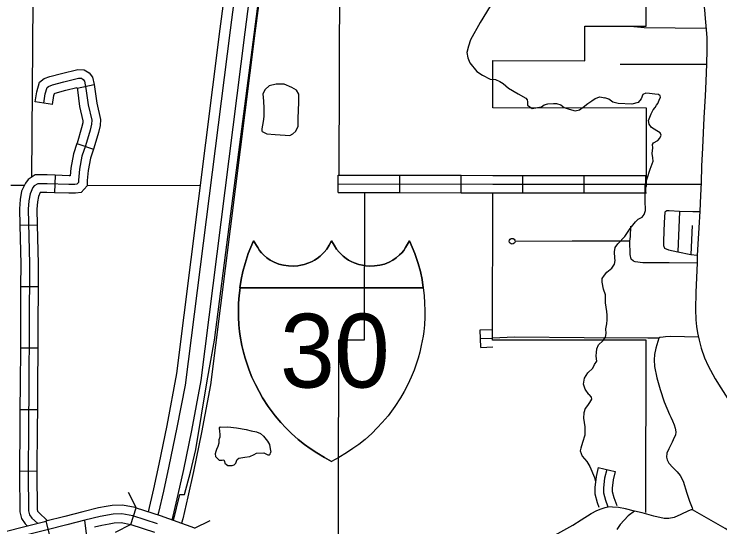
# Model space of a CAD drawing. Extents: x 813775 to 1157140, y 1757555 to 1979907.
# Drawn here: x 985663 to 997785, y 1859017 to 1867821 of the extents above; entities that cross this region are included whole.
import ezdxf

# ---------------------------------------------------------------- set-up
doc = ezdxf.new("R2010")
doc.units = 0
for name, color, linetype in [('Level 15', 7, 'Continuous'), ('Level 19', 7, 'Continuous'), ('Level 23', 7, 'Continuous'), ('Level 31', 7, 'Continuous'), ('Level 32', 7, 'Continuous'), ('Level 33', 7, 'Continuous'), ('Level 34', 7, 'Continuous'), ('Level 35', 7, 'Continuous'), ('Level 38', 7, 'Continuous'), ('Level 4', 7, 'Continuous'), ('Level 45', 7, 'Continuous'), ('Level 5', 7, 'Continuous'), ('Level 6', 7, 'Continuous'), ('Level 9', 7, 'Continuous')]:
    doc.layers.add(name, color=color, linetype=linetype)

msp = doc.modelspace()

# ---------------------------------------------------------------- linework, layer by layer
at = {"layer": 'Level 15'}
for points in [[(997102, 1871461), (997156, 1871024), (997216, 1870530), (997290, 1869822), (997389, 1868989), (997444, 1868499), (997480, 1868200), (997518, 1867894), (997531, 1867744), (997550, 1867556), (997558, 1867415), (997563, 1867292), (997560, 1867202), (997555, 1866966), (997541, 1866667), (997533, 1866416), (997511, 1866043), (997484, 1865525), (997470, 1865211), (997464, 1864930), (997453, 1864707), (997440, 1864440), (997423, 1864150), (997408, 1863873)], [(997408, 1863873), (997397, 1863676), (997393, 1863550), (997371, 1863040), (997368, 1862753), (997374, 1862572), (997381, 1862459), (997401, 1862349), (997429, 1862223), (997461, 1862088), (997523, 1861921), (997585, 1861780), (997703, 1861561), (997801, 1861403), (998031, 1861044), (998302, 1860636), (998495, 1860333), (998820, 1859828)]]:
    msp.add_lwpolyline(points, dxfattribs=at)
at = {"layer": 'Level 19'}
for points in [[(989204, 1867569), (989469, 1869607)], [(989637, 1869585), (989373, 1867548)], [(989631, 1867514), (989895, 1869552)], [(990064, 1869530), (989799, 1867492)], [(988455, 1861653), (989204, 1867569)], [(989373, 1867548), (988601, 1861451)], [(988873, 1861532), (989631, 1867514)], [(989799, 1867492), (989035, 1861457)], [(988061, 1859668), (988155, 1860095), (988293, 1860755), (988455, 1861653)], [(988480, 1859572), (988575, 1860003), (988714, 1860671), (988873, 1861532)], [(988601, 1861451), (988459, 1860722), (988321, 1860058), (988227, 1859630)], [(989035, 1861457), (988881, 1860637), (988741, 1859967), (988646, 1859534)], [(987971, 1859275), (988061, 1859668)], [(988227, 1859630), (988142, 1859264), (988131, 1859224)], [(988376, 1859137), (988394, 1859199), (988480, 1859572)], [(988646, 1859534), (988559, 1859156), (988537, 1859079)]]:
    msp.add_lwpolyline(points, dxfattribs=at)
at = {"layer": 'Level 23'}
msp.add_line((992691, 1863121), (992689, 1863121), dxfattribs=at)
for points in [[(989541, 1863121), (989563, 1863266), (989592, 1863404), (989629, 1863537), (989683, 1863708), (989776, 1863931), (989847, 1863813), (989878, 1863763), (989910, 1863724), (989948, 1863686), (990005, 1863638), (990063, 1863597), (990127, 1863561), (990209, 1863530), (990290, 1863510), (990376, 1863498), (990468, 1863496), (990534, 1863501), (990588, 1863508), (990646, 1863520), (990727, 1863550), (990780, 1863573), (990824, 1863596), (990867, 1863625), (990919, 1863665), (990986, 1863731), (991033, 1863788), (991072, 1863852), (991116, 1863928)], [(991116, 1863928), (991072, 1863852), (991033, 1863788), (990986, 1863731), (990919, 1863665), (990867, 1863625), (990824, 1863596), (990780, 1863573), (990727, 1863550), (990646, 1863520), (990588, 1863508), (990534, 1863501), (990468, 1863496), (990376, 1863498), (990290, 1863510), (990209, 1863530), (990127, 1863561), (990063, 1863597), (990005, 1863638), (989948, 1863686), (989910, 1863724), (989878, 1863763), (989847, 1863813), (989776, 1863931), (989683, 1863708), (989629, 1863537), (989592, 1863404), (989563, 1863266), (989541, 1863121)], [(991116, 1863928), (991159, 1863852), (991198, 1863788), (991246, 1863731), (991313, 1863665), (991364, 1863625), (991407, 1863596), (991451, 1863573), (991504, 1863550), (991586, 1863520), (991644, 1863508), (991698, 1863501), (991764, 1863496), (991855, 1863498), (991942, 1863510), (992022, 1863530), (992105, 1863561), (992168, 1863597), (992226, 1863638), (992283, 1863686), (992322, 1863724), (992354, 1863763), (992385, 1863813), (992455, 1863931), (992548, 1863708), (992602, 1863537), (992640, 1863404), (992669, 1863266), (992691, 1863121)], [(992691, 1863121), (992669, 1863266), (992640, 1863404), (992602, 1863537), (992548, 1863708), (992455, 1863931), (992385, 1863813), (992354, 1863763), (992322, 1863724), (992283, 1863686), (992226, 1863638), (992168, 1863597), (992105, 1863561), (992022, 1863530), (991942, 1863510), (991855, 1863498), (991764, 1863496), (991698, 1863501), (991644, 1863508), (991586, 1863520), (991504, 1863550), (991451, 1863573), (991407, 1863596), (991364, 1863625), (991313, 1863665), (991246, 1863731), (991198, 1863788), (991159, 1863852), (991116, 1863928)], [(989543, 1863121), (989527, 1862992), (989518, 1862857), (989514, 1862732), (989516, 1862619), (989523, 1862487), (989534, 1862373), (989546, 1862290), (989575, 1862130), (989602, 1862018), (989630, 1861916), (989663, 1861810), (989701, 1861705), (989747, 1861590), (989808, 1861459), (989869, 1861341), (989931, 1861233), (990027, 1861085), (990145, 1860926), (990245, 1860808), (990331, 1860715), (990427, 1860621), (990541, 1860519), (990648, 1860434), (990749, 1860360), (990860, 1860286), (990991, 1860208), (991116, 1860141)], [(991116, 1860141), (990991, 1860208), (990860, 1860286), (990749, 1860360), (990648, 1860434), (990541, 1860519), (990427, 1860621), (990331, 1860715), (990245, 1860808), (990145, 1860926), (990027, 1861085), (989931, 1861233), (989869, 1861341), (989808, 1861459), (989747, 1861590), (989701, 1861705), (989663, 1861810), (989630, 1861916), (989602, 1862018), (989575, 1862130), (989546, 1862290), (989534, 1862373), (989523, 1862487), (989516, 1862619), (989514, 1862732), (989518, 1862857), (989527, 1862992), (989543, 1863121)], [(992691, 1863121), (989541, 1863121)], [(989541, 1863121), (992691, 1863121)], [(989541, 1863121), (992691, 1863121)], [(992689, 1863121), (992704, 1862992), (992714, 1862857), (992717, 1862732), (992716, 1862619), (992709, 1862487), (992698, 1862373), (992686, 1862290), (992656, 1862130), (992630, 1862018), (992602, 1861916), (992569, 1861810), (992531, 1861705), (992484, 1861590), (992424, 1861459), (992362, 1861341), (992301, 1861233), (992204, 1861085), (992086, 1860926), (991987, 1860808), (991900, 1860715), (991805, 1860621), (991690, 1860519), (991584, 1860434), (991483, 1860360), (991372, 1860286), (991241, 1860208), (991116, 1860141)], [(992689, 1863121), (992704, 1862992), (992714, 1862857), (992717, 1862732), (992716, 1862619), (992709, 1862487), (992698, 1862373), (992686, 1862290), (992656, 1862130), (992630, 1862018), (992602, 1861916), (992569, 1861810), (992531, 1861705), (992484, 1861590), (992424, 1861459), (992362, 1861341), (992301, 1861233), (992204, 1861085), (992086, 1860926), (991987, 1860808), (991900, 1860715), (991805, 1860621), (991690, 1860519), (991584, 1860434), (991483, 1860360), (991372, 1860286), (991241, 1860208), (991116, 1860141)]]:
    msp.add_lwpolyline(points, dxfattribs=at)
at = {"layer": 'Level 31'}
for p, q in [((987666, 1859058), (987757, 1859344)), ((986207, 1859114), (986282, 1858823))]:
    msp.add_line(p, q, dxfattribs=at)
for points in [[(987244, 1859366), (987110, 1859342), (986841, 1859276), (986533, 1859197), (986207, 1859114)], [(987757, 1859344), (987740, 1859349), (987523, 1859390), (987348, 1859385), (987244, 1859366)], [(987757, 1859344), (988170, 1859211)], [(988124, 1859069), (987703, 1859204), (987511, 1859239), (987364, 1859235), (987141, 1859195), (986877, 1859131)], [(988170, 1859211), (988760, 1858999)], [(986877, 1859131), (986570, 1859052), (986229, 1858965), (985241, 1858717), (984617, 1858543), (983601, 1858139), (983057, 1857909), (982923, 1857851), (982300, 1857564)], [(985158, 1858851), (986192, 1859110), (986207, 1859114)], [(985214, 1854260), (985531, 1854943), (986022, 1856077), (986445, 1857082), (986766, 1857815), (986847, 1858007), (986914, 1858244), (986932, 1858516), (986918, 1858806), (986877, 1859131)], [(987297, 1859070), (987380, 1859085), (987500, 1859089), (987666, 1859058)], [(987043, 1859017), (987172, 1859048), (987297, 1859070)], [(987666, 1859058), (988076, 1858927)]]:
    msp.add_lwpolyline(points, dxfattribs=at)
at = {"layer": 'Level 32'}
for p, q in [((986743, 1866551), (987037, 1866612)), ((986321, 1866270), (986024, 1866316)), ((986740, 1865598), (987025, 1865504)), ((986366, 1865054), (986355, 1864754)), ((991231, 1864758), (991231, 1865058)), ((992287, 1864756), (992287, 1865056)), ((993343, 1864754), (993343, 1865054)), ((994399, 1864753), (994399, 1865053)), ((995455, 1864753), (995455, 1865053)), ((996511, 1864753), (996511, 1865053)), ((985760, 1864197), (986060, 1864205)), ((985774, 1863146), (986074, 1863145)), ((985770, 1862090), (986070, 1862089)), ((985762, 1861035), (986062, 1861031)), ((985754, 1859978), (986054, 1859976))]:
    msp.add_line(p, q, dxfattribs=at)
for points in [[(986024, 1866316), (986050, 1866486), (986098, 1866654), (986181, 1866714), (986278, 1866751), (986479, 1866804), (986755, 1866872), (986865, 1866867), (986950, 1866815), (987010, 1866737), (987037, 1866612)], [(987037, 1866612), (987045, 1866571), (987083, 1866291), (987147, 1866011), (987140, 1865907), (987111, 1865790), (987029, 1865517), (987025, 1865504)], [(986321, 1866270), (986344, 1866422), (986355, 1866459), (986370, 1866465), (986553, 1866514), (986741, 1866560), (986743, 1866551)], [(986743, 1866551), (986749, 1866520), (986788, 1866237), (986844, 1865987), (986842, 1865953), (986822, 1865869), (986743, 1865607), (986740, 1865598)], [(986740, 1865598), (986683, 1865423), (986635, 1865178), (986624, 1865046), (986606, 1865046), (986366, 1865054)], [(987025, 1865504), (986974, 1865347), (986932, 1865137), (986918, 1864965), (986918, 1864870), (986814, 1864758), (986715, 1864746), (986600, 1864746), (986355, 1864754)], [(986366, 1865054), (986231, 1865059), (986026, 1865059), (985903, 1864984), (985856, 1864921), (985792, 1864783), (985765, 1864636), (985754, 1864478), (985760, 1864197)], [(991231, 1865058), (992287, 1865056)], [(992287, 1865056), (993343, 1865054)], [(993343, 1865054), (993884, 1865053), (994399, 1865053)], [(994399, 1865053), (995455, 1865053)], [(995455, 1865053), (996511, 1865053)], [(996511, 1865053), (996522, 1865053)], [(991231, 1864908), (993883, 1864903), (996522, 1864903)], [(986355, 1864754), (986226, 1864759), (986111, 1864759), (986080, 1864692), (986063, 1864598), (986054, 1864471), (986060, 1864205)], [(991231, 1864758), (992287, 1864756)], [(992287, 1864756), (993343, 1864754)], [(993343, 1864754), (993883, 1864753), (994399, 1864753)], [(994399, 1864753), (995455, 1864753)], [(995455, 1864753), (996511, 1864753)], [(996511, 1864753), (996522, 1864753)], [(985760, 1864197), (985776, 1863530), (985774, 1863146)], [(986060, 1864205), (986076, 1863533), (986074, 1863145)], [(985774, 1863146), (985772, 1862478), (985770, 1862090)], [(986074, 1863145), (986072, 1862477), (986070, 1862089)], [(985770, 1862090), (985767, 1861460), (985762, 1861035)], [(986070, 1862089), (986067, 1861457), (986062, 1861031)], [(985762, 1861035), (985758, 1860720), (985754, 1859978)], [(986062, 1861031), (986058, 1860717), (986054, 1859976)], [(985754, 1859978), (985754, 1859938), (985758, 1859276), (985787, 1859160), (985853, 1859069), (985889, 1859034)], [(986054, 1859976), (986054, 1859938), (986058, 1859314), (986065, 1859288), (986079, 1859267), (986235, 1859121)]]:
    msp.add_lwpolyline(points, dxfattribs=at)
at = {"layer": 'Level 33'}
for points in [[(997548, 1867577), (996482, 1867584)], [(997554, 1866957), (996073, 1866954)], [(996522, 1864903), (997464, 1864900)], [(997439, 1864426), (997322, 1864426), (997090, 1864432), (996913, 1864442), (996871, 1864442), (996838, 1864419), (996828, 1864246), (996818, 1863931), (996818, 1863849), (996835, 1863800), (996900, 1863774), (997061, 1863738), (997286, 1863692), (997397, 1863684)], [(997090, 1864432), (997061, 1863738)], [(996239, 1863925), (996250, 1864000), (996253, 1864183)], [(997311, 1864194), (997286, 1863692)], [(997393, 1863544), (996916, 1863548), (996462, 1863551), (996331, 1863568), (996301, 1863581), (996262, 1863613), (996242, 1863695), (996239, 1863925), (995248, 1863925), (994267, 1863916)], [(996736, 1862255), (996550, 1862257)], [(996736, 1862255), (996685, 1862083), (996661, 1861979), (996654, 1861884), (996659, 1861771), (996703, 1861576), (996759, 1861376), (996826, 1861165), (996918, 1860945), (996944, 1860898), (996971, 1860836), (996998, 1860768), (997016, 1860709), (997026, 1860647)], [(997417, 1862277), (996939, 1862283), (996851, 1862278), (996810, 1862273), (996756, 1862267), (996736, 1862255)], [(997026, 1860647), (997023, 1860593), (997001, 1860552), (996967, 1860473), (996906, 1860354), (996875, 1860282), (996869, 1860216), (996877, 1860170), (996906, 1860110), (996975, 1860036), (997052, 1859962), (997101, 1859900), (997153, 1859803), (997217, 1859596), (997263, 1859460), (997300, 1859373), (997310, 1859344), (997313, 1859323), (997313, 1859309)], [(995257, 1859048), (995404, 1859137), (995572, 1859247), (995670, 1859297), (995748, 1859328), (995816, 1859348), (995866, 1859358)], [(997313, 1859309), (997289, 1859308), (997243, 1859294), (997112, 1859232), (997001, 1859180), (996906, 1859160), (996830, 1859163), (996650, 1859203), (996451, 1859255), (996317, 1859288), (996166, 1859327), (996042, 1859347), (995938, 1859355), (995866, 1859358)], [(996317, 1859288), (996209, 1859209), (996071, 1859055), (996012, 1858970)], [(999772, 1858327), (999353, 1858300), (999111, 1858283), (998888, 1858286), (998784, 1858296), (998715, 1858323), (998617, 1858381), (998460, 1858513), (998339, 1858647), (998204, 1858765), (998044, 1858883), (997874, 1858988), (997313, 1859309)], [(990956, 1857934), (991064, 1857851), (991174, 1857795), (991348, 1857732), (991660, 1857662), (991967, 1857608), (992186, 1857599), (992457, 1857632), (992518, 1857644), (992652, 1857680), (992811, 1857732), (993056, 1857824), (993309, 1857952), (993593, 1858093), (993826, 1858221), (994171, 1858429), (994407, 1858577), (994576, 1858666), (995000, 1858902), (995257, 1859048)]]:
    msp.add_lwpolyline(points, dxfattribs=at)
msp.add_circle((994217, 1863921), 50, dxfattribs=at)
at = {"layer": 'Level 34'}
for points in [[(996482, 1867584), (996250, 1867610)], [(996550, 1862257), (995453, 1862260), (994255, 1862273), (993878, 1862256)], [(995866, 1859358), (995855, 1859378)]]:
    msp.add_lwpolyline(points, dxfattribs=at)
at = {"layer": 'Level 35'}
for points in [[(994156, 1869444), (994265, 1869191), (994323, 1869031), (994328, 1868872), (994313, 1868771), (994270, 1868632), (994185, 1868462), (994089, 1868340), (993967, 1868138), (993840, 1867957), (993665, 1867675), (993500, 1867378), (993468, 1867271), (993441, 1867165), (993457, 1867069), (993489, 1866984)], [(993489, 1866984), (993613, 1866838), (993708, 1866775), (993841, 1866703), (993929, 1866697), (994003, 1866666), (994064, 1866631), (994155, 1866551)], [(989925, 1865806), (990002, 1865763), (990146, 1865755), (990318, 1865742), (990398, 1865739), (990448, 1865768), (990499, 1865811), (990541, 1865899), (990544, 1866031), (990555, 1866311), (990552, 1866446), (990512, 1866518), (990435, 1866563), (990302, 1866616), (990162, 1866619), (990045, 1866592), (989976, 1866529), (989936, 1866451), (989946, 1866324), (989954, 1866207), (989949, 1866063), (989941, 1865976), (989920, 1865853), (989920, 1865808)], [(994155, 1866551), (994319, 1866450), (994454, 1866376)], [(994454, 1866376), (994473, 1866352), (994478, 1866315), (994483, 1866259), (994563, 1866198), (994653, 1866219), (994722, 1866232), (994767, 1866261), (994831, 1866283), (994927, 1866285), (994980, 1866288), (995052, 1866261), (995113, 1866219), (995198, 1866190), (995301, 1866163), (995376, 1866179), (995439, 1866222), (995516, 1866285), (995583, 1866333), (995641, 1866370), (995724, 1866400), (995808, 1866385)], [(996036, 1866284), (995946, 1866311), (995877, 1866359), (995808, 1866385)], [(996740, 1866343), (996764, 1866398), (996761, 1866417), (996732, 1866441), (996666, 1866449), (996578, 1866460), (996514, 1866462), (996464, 1866441), (996435, 1866369), (996382, 1866303), (996273, 1866274), (996036, 1866284)], [(996642, 1865610), (996719, 1865651), (996756, 1865689), (996778, 1865745), (996759, 1865782), (996700, 1865816), (996611, 1865872), (996571, 1865933), (996557, 1865997), (996581, 1866050), (996602, 1866109), (996639, 1866178), (996671, 1866220), (996698, 1866260), (996719, 1866287), (996740, 1866343)], [(996501, 1864891), (996538, 1865001), (996589, 1865160), (996639, 1865296), (996634, 1865354), (996621, 1865426), (996631, 1865527), (996626, 1865583), (996642, 1865610)], [(996336, 1864255), (996384, 1864303), (996451, 1864333), (996485, 1864378), (996506, 1864450), (996504, 1864620), (996501, 1864891)], [(995983, 1863628), (995973, 1863742), (995986, 1863812), (996034, 1863875), (996151, 1864003), (996243, 1864138), (996336, 1864255)], [(995930, 1863460), (995975, 1863525), (995989, 1863591), (995983, 1863628)], [(995827, 1862416), (995842, 1862506), (995850, 1862572), (995848, 1862654), (995842, 1862716), (995821, 1862864), (995819, 1863003), (995787, 1863101), (995763, 1863218), (995765, 1863279), (995803, 1863340), (995842, 1863391), (995930, 1863460)], [(995532, 1861291), (995471, 1861384), (995441, 1861467), (995460, 1861571), (995516, 1861661), (995601, 1861741), (995630, 1861802), (995670, 1861861), (995667, 1861903), (995659, 1861954), (995665, 1862010), (995672, 1862076), (995702, 1862142), (995773, 1862212), (995821, 1862273), (995834, 1862339), (995827, 1862416)], [(995532, 1861291), (995572, 1861243), (995579, 1861208), (995545, 1861152), (995510, 1861099), (995473, 1861051), (995447, 1860977), (995441, 1860884)], [(995441, 1860884), (995465, 1860732), (995468, 1860591), (995425, 1860464), (995394, 1860368), (995386, 1860323), (995417, 1860233), (995497, 1860140), (995553, 1860052)], [(989208, 1860728), (989184, 1860723), (989191, 1860651), (989197, 1860616), (989196, 1860558), (989181, 1860511), (989176, 1860454), (989161, 1860397), (989136, 1860344), (989127, 1860312), (989116, 1860271), (989119, 1860227), (989155, 1860188), (989187, 1860162), (989215, 1860160), (989237, 1860164), (989266, 1860166), (989278, 1860142), (989284, 1860111), (989309, 1860087), (989333, 1860071), (989378, 1860069), (989406, 1860071), (989444, 1860081), (989471, 1860113), (989489, 1860160), (989496, 1860176), (989521, 1860195), (989554, 1860202), (989628, 1860214), (989710, 1860224), (989788, 1860260), (989823, 1860283), (989952, 1860287), (989987, 1860271), (990021, 1860251), (990043, 1860252), (990063, 1860265), (990066, 1860287), (990071, 1860299)], [(989208, 1860728), (989331, 1860732), (989483, 1860720), (989650, 1860687), (989732, 1860668), (989824, 1860649), (989892, 1860620), (989945, 1860575), (990014, 1860487), (990047, 1860429), (990062, 1860354), (990071, 1860299)], [(995553, 1860052), (995633, 1859864), (995648, 1859800)]]:
    msp.add_lwpolyline(points, dxfattribs=at)
at = {"layer": 'Level 38'}
for points in [[(987619, 1859611), (987757, 1859344)], [(988759, 1858997), (989030, 1859125)], [(987666, 1859058), (987399, 1858921)]]:
    msp.add_lwpolyline(points, dxfattribs=at)
at = {"layer": 'Level 4'}
msp.add_lwpolyline([(986040, 1875566), (985961, 1865019)], dxfattribs=at)
at = {"layer": 'Level 45'}
for p, q in [((993678, 1862099), (993668, 1862399)), ((995695, 1860038), (995987, 1859968))]:
    msp.add_line(p, q, dxfattribs=at)
for points in [[(993668, 1862399), (993873, 1862406)], [(993673, 1862249), (993878, 1862256)], [(993678, 1862099), (993883, 1862106)], [(995695, 1860038), (995657, 1859880), (995635, 1859695), (995638, 1859582), (995677, 1859433), (995705, 1859354)], [(995841, 1860003), (995805, 1859853), (995785, 1859688), (995787, 1859603), (995821, 1859476), (995855, 1859378)], [(995987, 1859968), (995953, 1859827), (995935, 1859681), (995937, 1859625), (995964, 1859520), (996012, 1859383)]]:
    msp.add_lwpolyline(points, dxfattribs=at)
at = {"layer": 'Level 5'}
for points in [[(985609, 1864886), (985839, 1864885)], [(986918, 1864882), (988864, 1864878)]]:
    msp.add_lwpolyline(points, dxfattribs=at)
at = {"layer": 'Level 6'}
for points in [[(996508, 1864862), (996524, 1864862), (996522, 1866205), (993884, 1866211), (993884, 1867022), (995463, 1867019), (995463, 1867615), (996519, 1867613), (996515, 1869564), (995200, 1869566), (995200, 1870238), (995198, 1872879), (996509, 1872882), (996786, 1872879)], [(988398, 1859129), (988509, 1859570), (988587, 1859570), (988690, 1859956), (988781, 1860346), (988977, 1861523), (989103, 1862224), (989445, 1864877), (990146, 1870247), (991257, 1870245), (991242, 1865051)], [(991682, 1864757), (991675, 1862223), (991235, 1862223)], [(996513, 1859264), (996519, 1862221), (993877, 1862222), (993883, 1864752)], [(991235, 1862223), (991229, 1859573), (991226, 1858262), (992094, 1857986), (992093, 1857634)]]:
    msp.add_lwpolyline(points, dxfattribs=at)
at = {"layer": 'Level 9'}
for points in [[(986173, 1866293), (986197, 1866454), (986228, 1866563), (986253, 1866581), (986324, 1866608), (986516, 1866659), (986770, 1866722), (986819, 1866719), (986848, 1866701), (986871, 1866672), (986897, 1866545)], [(986897, 1866545), (986935, 1866264), (986996, 1865999), (986991, 1865930), (986967, 1865830), (986886, 1865562)], [(986886, 1865562), (986828, 1865385), (986784, 1865158), (986768, 1864972), (986768, 1864929), (986741, 1864900), (986706, 1864896), (986603, 1864896), (986228, 1864909), (986068, 1864909), (986005, 1864871), (985985, 1864844), (985936, 1864737), (985914, 1864617), (985904, 1864474)], [(985904, 1864474), (985926, 1863531), (985922, 1862477), (985917, 1861458), (985908, 1860718), (985904, 1859938), (985908, 1859295), (985926, 1859224), (985966, 1859168), (986062, 1859078)]]:
    msp.add_lwpolyline(points, dxfattribs=at)

# ---------------------------------------------------------------- texts
at = {"layer": 'Level 23'}
msp.add_text('30', height=1267.2, dxfattribs=at).set_placement((990229, 1861409))
at = {"layer": 'Level 35'}
msp.add_text('Caney', height=844.8, rotation=58.5196, dxfattribs=at).set_placement((984242, 1866943))

doc.saveas('drawing.dxf')
